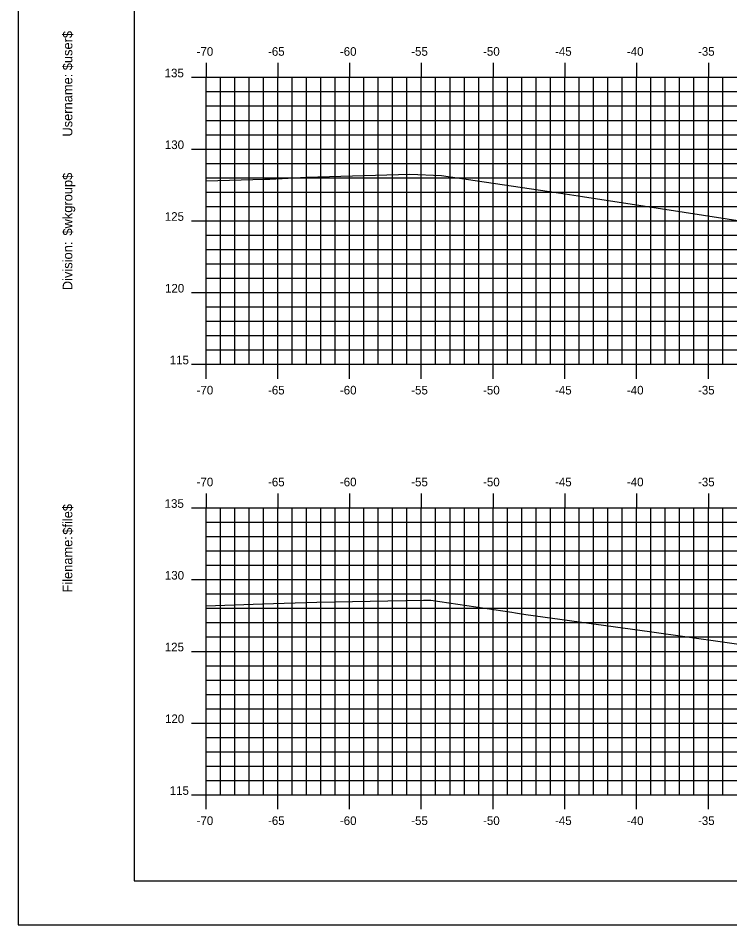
# Model space of a CAD drawing. Extents: x 851295 to 851467, y 365624 to 365734.
# Drawn here: x 851294.9 to 851344.5, y 365624 to 365687.1 of the extents above; entities that cross this region are included whole.
import ezdxf

# ---------------------------------------------------------------- set-up
doc = ezdxf.new("R2010")
doc.units = 0
for name, color, linetype in [('BORDER', 7, 'Continuous'), ('H_V ANNOTATION', 7, 'Continuous'), ('MAJOR', 7, 'Continuous'), ('MINOR', 7, 'Continuous'), ('PLOT BOUNDARY', 7, 'Continuous'), ('S_Roadway_Centerline', 7, 'Continuous')]:
    doc.layers.add(name, color=color, linetype=linetype)

msp = doc.modelspace()

# ---------------------------------------------------------------- linework, layer by layer
at = {"layer": 'BORDER'}
msp.add_lwpolyline([(851303.009, 365627.027), (851463.009, 365627.027), (851463.009, 365732.027), (851303.009, 365732.027)], close=True, dxfattribs=at)
at = {"layer": 'MAJOR'}
for p, q in [((851308.009, 365684.029), (851308.009, 365683.027)), ((851313.009, 365684.029), (851313.009, 365683.027)), ((851318.009, 365684.029), (851318.009, 365683.027)), ((851323.009, 365684.029), (851323.009, 365683.027)), ((851328.009, 365684.029), (851328.009, 365683.027)), ((851333.009, 365684.029), (851333.009, 365683.027)), ((851338.009, 365684.029), (851338.009, 365683.027)), ((851343.009, 365684.029), (851343.009, 365683.027)), ((851307.007, 365683.027), (851308.009, 365683.027)), ((851308.009, 365683.027), (851448.009, 365683.027)), ((851308.009, 365663.027), (851308.009, 365683.027)), ((851308.009, 365663.027), (851308.009, 365683.027)), ((851308.009, 365683.027), (851448.009, 365683.027)), ((851313.009, 365663.027), (851313.009, 365683.027)), ((851318.009, 365663.027), (851318.009, 365683.027)), ((851323.009, 365663.027), (851323.009, 365683.027)), ((851328.009, 365663.027), (851328.009, 365683.027)), ((851333.009, 365663.027), (851333.009, 365683.027)), ((851338.009, 365663.027), (851338.009, 365683.027)), ((851343.009, 365663.027), (851343.009, 365683.027)), ((851307.007, 365678.027), (851308.009, 365678.027)), ((851308.009, 365678.027), (851448.009, 365678.027)), ((851307.007, 365673.027), (851308.009, 365673.027)), ((851308.009, 365673.027), (851448.009, 365673.027)), ((851307.007, 365668.027), (851308.009, 365668.027)), ((851308.009, 365668.027), (851448.009, 365668.027)), ((851307.007, 365663.027), (851308.009, 365663.027)), ((851308.009, 365663.027), (851448.009, 365663.027)), ((851308.009, 365663.027), (851448.009, 365663.027)), ((851308.009, 365662.025), (851308.009, 365663.027)), ((851313.009, 365662.025), (851313.009, 365663.027)), ((851318.009, 365662.025), (851318.009, 365663.027)), ((851323.009, 365662.025), (851323.009, 365663.027)), ((851328.009, 365662.025), (851328.009, 365663.027)), ((851333.009, 365662.025), (851333.009, 365663.027)), ((851338.009, 365662.025), (851338.009, 365663.027)), ((851343.009, 365662.025), (851343.009, 365663.027)), ((851308.009, 365654.029), (851308.009, 365653.027)), ((851313.009, 365654.029), (851313.009, 365653.027)), ((851318.009, 365654.029), (851318.009, 365653.027)), ((851323.009, 365654.029), (851323.009, 365653.027)), ((851328.009, 365654.029), (851328.009, 365653.027)), ((851333.009, 365654.029), (851333.009, 365653.027)), ((851338.009, 365654.029), (851338.009, 365653.027)), ((851343.009, 365654.029), (851343.009, 365653.027)), ((851307.007, 365653.027), (851308.009, 365653.027)), ((851308.009, 365653.027), (851448.009, 365653.027)), ((851308.009, 365633.027), (851308.009, 365653.027)), ((851308.009, 365633.027), (851308.009, 365653.027)), ((851308.009, 365653.027), (851448.009, 365653.027)), ((851313.009, 365633.027), (851313.009, 365653.027)), ((851318.009, 365633.027), (851318.009, 365653.027)), ((851323.009, 365633.027), (851323.009, 365653.027)), ((851328.009, 365633.027), (851328.009, 365653.027)), ((851333.009, 365633.027), (851333.009, 365653.027)), ((851338.009, 365633.027), (851338.009, 365653.027)), ((851343.009, 365633.027), (851343.009, 365653.027)), ((851307.007, 365648.027), (851308.009, 365648.027)), ((851308.009, 365648.027), (851448.009, 365648.027)), ((851307.007, 365643.027), (851308.009, 365643.027)), ((851308.009, 365643.027), (851448.009, 365643.027)), ((851307.007, 365638.027), (851308.009, 365638.027)), ((851308.009, 365638.027), (851448.009, 365638.027)), ((851307.007, 365633.027), (851308.009, 365633.027)), ((851308.009, 365633.027), (851448.009, 365633.027)), ((851308.009, 365633.027), (851448.009, 365633.027)), ((851308.009, 365632.025), (851308.009, 365633.027)), ((851313.009, 365632.025), (851313.009, 365633.027)), ((851318.009, 365632.025), (851318.009, 365633.027)), ((851323.009, 365632.025), (851323.009, 365633.027)), ((851328.009, 365632.025), (851328.009, 365633.027)), ((851333.009, 365632.025), (851333.009, 365633.027)), ((851338.009, 365632.025), (851338.009, 365633.027)), ((851343.009, 365632.025), (851343.009, 365633.027))]:
    msp.add_line(p, q, dxfattribs=at)
at = {"layer": 'MINOR'}
for p, q in [((851309.009, 365663.027), (851309.009, 365683.027)), ((851310.009, 365663.027), (851310.009, 365683.027)), ((851311.009, 365663.027), (851311.009, 365683.027)), ((851312.009, 365663.027), (851312.009, 365683.027)), ((851314.009, 365663.027), (851314.009, 365683.027)), ((851315.009, 365663.027), (851315.009, 365683.027)), ((851316.009, 365663.027), (851316.009, 365683.027)), ((851317.009, 365663.027), (851317.009, 365683.027)), ((851319.009, 365663.027), (851319.009, 365683.027)), ((851320.009, 365663.027), (851320.009, 365683.027)), ((851321.009, 365663.027), (851321.009, 365683.027)), ((851322.009, 365663.027), (851322.009, 365683.027)), ((851324.009, 365663.027), (851324.009, 365683.027)), ((851325.009, 365663.027), (851325.009, 365683.027)), ((851326.009, 365663.027), (851326.009, 365683.027)), ((851327.009, 365663.027), (851327.009, 365683.027)), ((851329.009, 365663.027), (851329.009, 365683.027)), ((851330.009, 365663.027), (851330.009, 365683.027)), ((851331.009, 365663.027), (851331.009, 365683.027)), ((851332.009, 365663.027), (851332.009, 365683.027)), ((851334.009, 365663.027), (851334.009, 365683.027)), ((851335.009, 365663.027), (851335.009, 365683.027)), ((851336.009, 365663.027), (851336.009, 365683.027)), ((851337.009, 365663.027), (851337.009, 365683.027)), ((851339.009, 365663.027), (851339.009, 365683.027)), ((851340.009, 365663.027), (851340.009, 365683.027)), ((851341.009, 365663.027), (851341.009, 365683.027)), ((851342.009, 365663.027), (851342.009, 365683.027)), ((851344.009, 365663.027), (851344.009, 365683.027)), ((851308.009, 365682.027), (851448.009, 365682.027)), ((851308.009, 365682.027), (851309.011, 365682.027)), ((851308.009, 365681.027), (851448.009, 365681.027)), ((851308.009, 365681.027), (851309.011, 365681.027)), ((851308.009, 365680.027), (851448.009, 365680.027)), ((851308.009, 365680.027), (851309.011, 365680.027)), ((851308.009, 365679.027), (851448.009, 365679.027)), ((851308.009, 365679.027), (851309.011, 365679.027)), ((851308.009, 365677.027), (851448.009, 365677.027)), ((851308.009, 365677.027), (851309.011, 365677.027)), ((851308.009, 365676.027), (851448.009, 365676.027)), ((851308.009, 365676.027), (851309.011, 365676.027)), ((851308.009, 365675.027), (851448.009, 365675.027)), ((851308.009, 365675.027), (851309.011, 365675.027)), ((851308.009, 365674.027), (851448.009, 365674.027)), ((851308.009, 365674.027), (851309.011, 365674.027)), ((851308.009, 365672.027), (851448.009, 365672.027)), ((851308.009, 365672.027), (851309.011, 365672.027)), ((851308.009, 365671.027), (851448.009, 365671.027)), ((851308.009, 365671.027), (851309.011, 365671.027)), ((851308.009, 365670.027), (851448.009, 365670.027)), ((851308.009, 365670.027), (851309.011, 365670.027)), ((851308.009, 365669.027), (851448.009, 365669.027)), ((851308.009, 365669.027), (851309.011, 365669.027)), ((851308.009, 365667.027), (851448.009, 365667.027)), ((851308.009, 365667.027), (851309.011, 365667.027)), ((851308.009, 365666.027), (851448.009, 365666.027)), ((851308.009, 365666.027), (851309.011, 365666.027)), ((851308.009, 365665.027), (851448.009, 365665.027)), ((851308.009, 365665.027), (851309.011, 365665.027)), ((851308.009, 365664.027), (851448.009, 365664.027)), ((851308.009, 365664.027), (851309.011, 365664.027)), ((851309.009, 365633.027), (851309.009, 365653.027)), ((851310.009, 365633.027), (851310.009, 365653.027)), ((851311.009, 365633.027), (851311.009, 365653.027)), ((851312.009, 365633.027), (851312.009, 365653.027)), ((851314.009, 365633.027), (851314.009, 365653.027)), ((851315.009, 365633.027), (851315.009, 365653.027)), ((851316.009, 365633.027), (851316.009, 365653.027)), ((851317.009, 365633.027), (851317.009, 365653.027)), ((851319.009, 365633.027), (851319.009, 365653.027)), ((851320.009, 365633.027), (851320.009, 365653.027)), ((851321.009, 365633.027), (851321.009, 365653.027)), ((851322.009, 365633.027), (851322.009, 365653.027)), ((851324.009, 365633.027), (851324.009, 365653.027)), ((851325.009, 365633.027), (851325.009, 365653.027)), ((851326.009, 365633.027), (851326.009, 365653.027)), ((851327.009, 365633.027), (851327.009, 365653.027)), ((851329.009, 365633.027), (851329.009, 365653.027)), ((851330.009, 365633.027), (851330.009, 365653.027)), ((851331.009, 365633.027), (851331.009, 365653.027)), ((851332.009, 365633.027), (851332.009, 365653.027)), ((851334.009, 365633.027), (851334.009, 365653.027)), ((851335.009, 365633.027), (851335.009, 365653.027)), ((851336.009, 365633.027), (851336.009, 365653.027)), ((851337.009, 365633.027), (851337.009, 365653.027)), ((851339.009, 365633.027), (851339.009, 365653.027)), ((851340.009, 365633.027), (851340.009, 365653.027)), ((851341.009, 365633.027), (851341.009, 365653.027)), ((851342.009, 365633.027), (851342.009, 365653.027)), ((851344.009, 365633.027), (851344.009, 365653.027)), ((851308.009, 365652.027), (851448.009, 365652.027)), ((851308.009, 365652.027), (851309.011, 365652.027)), ((851308.009, 365651.027), (851448.009, 365651.027)), ((851308.009, 365651.027), (851309.011, 365651.027)), ((851308.009, 365650.027), (851448.009, 365650.027)), ((851308.009, 365650.027), (851309.011, 365650.027)), ((851308.009, 365649.027), (851448.009, 365649.027)), ((851308.009, 365649.027), (851309.011, 365649.027)), ((851308.009, 365647.027), (851448.009, 365647.027)), ((851308.009, 365647.027), (851309.011, 365647.027)), ((851308.009, 365646.027), (851448.009, 365646.027)), ((851308.009, 365646.027), (851309.011, 365646.027)), ((851308.009, 365645.027), (851448.009, 365645.027)), ((851308.009, 365645.027), (851309.011, 365645.027)), ((851308.009, 365644.027), (851448.009, 365644.027)), ((851308.009, 365644.027), (851309.011, 365644.027)), ((851308.009, 365642.027), (851448.009, 365642.027)), ((851308.009, 365642.027), (851309.011, 365642.027)), ((851308.009, 365641.027), (851448.009, 365641.027)), ((851308.009, 365641.027), (851309.011, 365641.027)), ((851308.009, 365640.027), (851448.009, 365640.027)), ((851308.009, 365640.027), (851309.011, 365640.027)), ((851308.009, 365639.027), (851448.009, 365639.027)), ((851308.009, 365639.027), (851309.011, 365639.027)), ((851308.009, 365637.027), (851448.009, 365637.027)), ((851308.009, 365637.027), (851309.011, 365637.027)), ((851308.009, 365636.027), (851448.009, 365636.027)), ((851308.009, 365636.027), (851309.011, 365636.027)), ((851308.009, 365635.027), (851448.009, 365635.027)), ((851308.009, 365635.027), (851309.011, 365635.027)), ((851308.009, 365634.027), (851448.009, 365634.027)), ((851308.009, 365634.027), (851309.011, 365634.027))]:
    msp.add_line(p, q, dxfattribs=at)
at = {"layer": 'PLOT BOUNDARY'}
msp.add_lwpolyline([(851294.916, 365623.968), (851464.916, 365623.968), (851464.916, 365733.968), (851294.916, 365733.968)], close=True, dxfattribs=at)
at = {"layer": 'S_Roadway_Centerline'}
for points in [[(851308.009, 365675.813), (851312.084, 365675.932), (851312.445, 365675.937), (851315.003, 365676.07), (851322.211, 365676.269), (851324.411, 365676.188), (851333.03, 365674.916), (851334.236, 365674.715), (851341.329, 365673.638), (851348.657, 365672.481), (851350.032, 365672.35), (851350.133, 365672.476), (851353.011, 365672.688), (851359.173, 365673.57), (851369.119, 365675.289), (851373.98, 365675.895), (851376.532, 365676.152), (851378.747, 365676.283), (851387.192, 365676.691), (851392.071, 365677.045), (851392.707, 365677.023), (851396.692, 365677.186)], [(851308.009, 365646.198), (851311.951, 365646.335), (851315.739, 365646.443), (851323.169, 365646.595), (851323.675, 365646.586), (851329.312, 365645.752), (851329.563, 365645.712), (851330.289, 365645.587), (851338.912, 365644.4), (851349.404, 365642.917), (851349.749, 365642.867), (851349.863, 365642.855), (851349.867, 365642.85), (851354.606, 365643.511), (851363.283, 365644.706), (851364.42, 365644.876), (851375.456, 365646.49), (851377.185, 365646.568), (851382.249, 365646.825), (851390.604, 365647.344), (851391.561, 365647.414), (851391.713, 365647.416), (851396.158, 365647.634)]]:
    msp.add_lwpolyline(points, dxfattribs=at)

# ---------------------------------------------------------------- texts
at = {"layer": 'BORDER'}
for s, p in [('$user$', (851298.694, 365683.518)), ('Username:', (851298.694, 365678.895)), ('$wkgroup$', (851298.694, 365671.996)), ('Division:', (851298.694, 365668.193)), ('$file$', (851298.694, 365651.152)), ('Filename:', (851298.694, 365647.125))]:
    msp.add_text(s, height=0.6696, rotation=90, dxfattribs=at).set_placement(p)
at = {"layer": 'H_V ANNOTATION'}
for s, p in [('-70', (851307.351, 365684.527)), ('-65', (851312.327, 365684.527)), ('-60', (851317.335, 365684.527)), ('-55', (851322.305, 365684.527)), ('-50', (851327.313, 365684.527)), ('-45', (851332.327, 365684.527)), ('-40', (851337.335, 365684.527)), ('-35', (851342.289, 365684.527)), ('135', (851305.123, 365683.027)), ('130', (851305.139, 365678.027)), ('125', (851305.134, 365673.027)), ('120', (851305.15, 365668.027)), ('115', (851305.476, 365663.027)), ('-70', (851307.351, 365660.927)), ('-65', (851312.327, 365660.927)), ('-60', (851317.335, 365660.927)), ('-55', (851322.305, 365660.927)), ('-50', (851327.313, 365660.927)), ('-45', (851332.327, 365660.927)), ('-40', (851337.335, 365660.927)), ('-35', (851342.289, 365660.927)), ('-70', (851307.351, 365654.527)), ('-65', (851312.327, 365654.527)), ('-60', (851317.335, 365654.527)), ('-55', (851322.305, 365654.527)), ('-50', (851327.313, 365654.527)), ('-45', (851332.327, 365654.527)), ('-40', (851337.335, 365654.527)), ('-35', (851342.289, 365654.527)), ('135', (851305.123, 365653.027)), ('130', (851305.139, 365648.027)), ('125', (851305.134, 365643.027)), ('120', (851305.15, 365638.027)), ('115', (851305.476, 365633.027)), ('-70', (851307.351, 365630.927)), ('-65', (851312.327, 365630.927)), ('-60', (851317.335, 365630.927)), ('-55', (851322.305, 365630.927)), ('-50', (851327.313, 365630.927)), ('-45', (851332.327, 365630.927)), ('-40', (851337.335, 365630.927)), ('-35', (851342.289, 365630.927))]:
    msp.add_text(s, height=0.6, dxfattribs=at).set_placement(p)
at = {"layer": 'MAJOR'}
for p in [(851308.005, 365663.027), (851308.005, 365633.027)]:
    msp.add_text('-', height=0.006, dxfattribs=at).set_placement(p)

doc.saveas('drawing.dxf')
